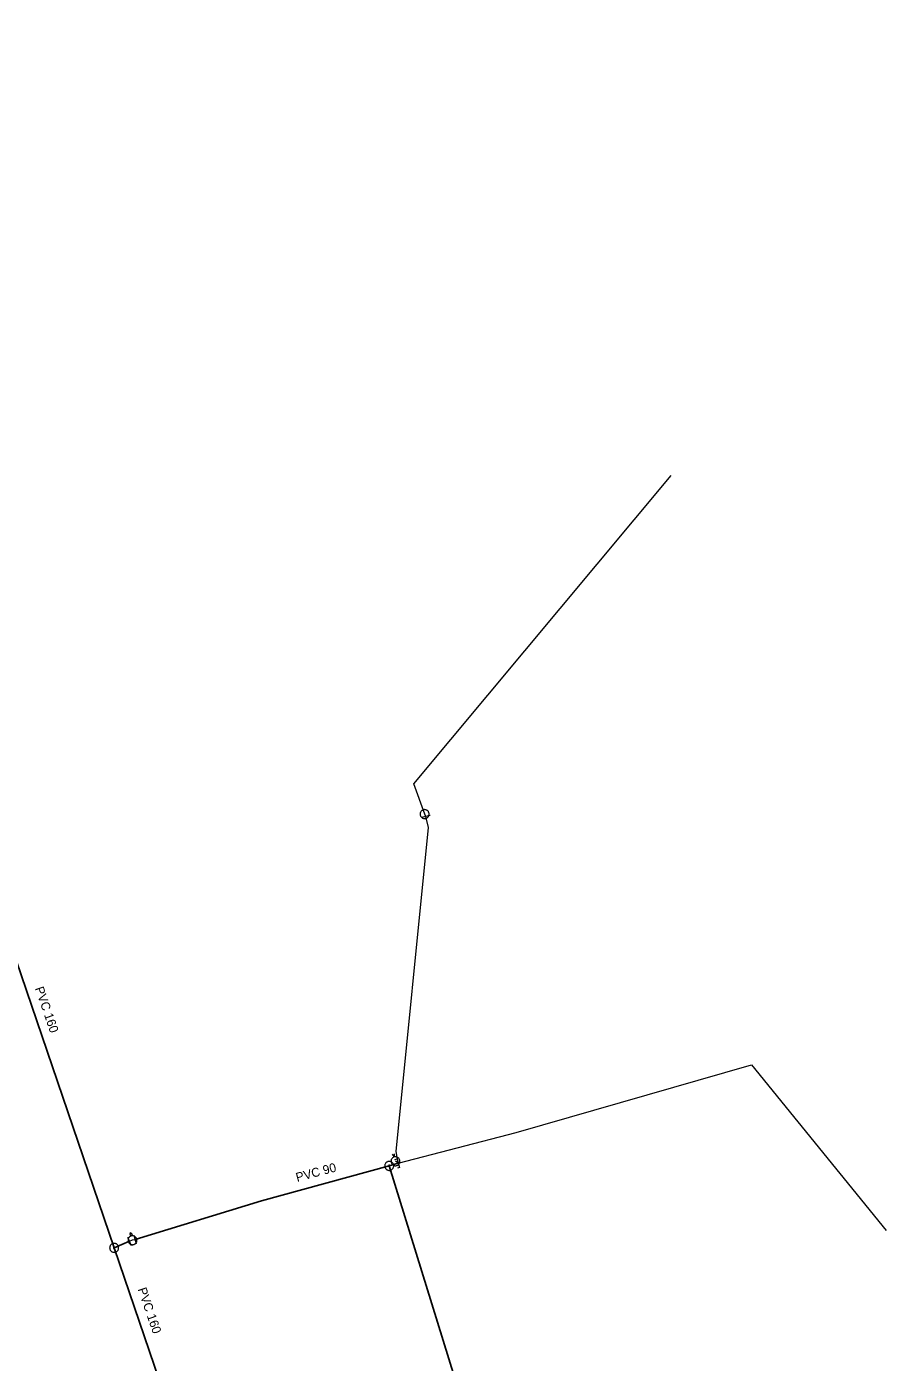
# Model space of a CAD drawing. Extents: x -659250 to -657316, y -997555 to -993684.
# Drawn here: x -658539.7 to -658443.8, y -995411.3 to -995262.3 of the extents above; entities that cross this region are included whole.
import ezdxf

# ---------------------------------------------------------------- set-up
doc = ezdxf.new("R2010")
doc.units = 0
doc.header["$LTSCALE"] = 0.4
doc.layers.add('1', color=7, linetype='Continuous')
for name, color, linetype, lineweight in [('13', 7, 'Continuous', 13), ('14', 7, 'Continuous', 25), ('17', 7, 'Continuous', 25), ('23', 7, 'Continuous', 13), ('34', 7, 'Continuous', 13), ('47', 7, 'Continuous', 13)]:
    doc.layers.add(name, color=color, linetype=linetype, lineweight=lineweight)

msp = doc.modelspace()

# ---------------------------------------------------------------- linework, layer by layer
at = {"layer": '13'}
for points in [[(-658495.287, -995350.184), (-658496.524, -995346.776), (-658467.787, -995312.381)], [(-658498.252, -995389.133), (-658498.48, -995387.811), (-658494.883, -995351.653), (-658495.19, -995350.441)], [(-658498.252, -995389.133), (-658485.079, -995385.693), (-658458.831, -995378.138), (-658443.765, -995396.647)]]:
    msp.add_lwpolyline(points, dxfattribs=at)
at = {"layer": '14', "lineweight": 13}
for p, q in [((-658495.19, -995350.441), (-658495.287, -995350.184)), ((-658498.252, -995389.133), (-658498.57, -995388.914))]:
    msp.add_line(p, q, dxfattribs=at)
msp.add_lwpolyline([(-658528.268, -995397.839), (-658527.915, -995397.698), (-658527.649, -995397.631)], dxfattribs=at)
at = {"layer": '17'}
for points in [[(-658529.982, -995398.576), (-658547.296, -995347.916), (-658562.807, -995322.499), (-658567.693, -995312.894), (-658572.046, -995279.881), (-658571.688, -995265.649), (-658570.911, -995262.293)], [(-658527.649, -995397.631), (-658513.52, -995393.331), (-658499.267, -995389.429), (-658498.252, -995389.133)], [(-658499.267, -995389.429), (-658490.855, -995416.603), (-658471.482, -995471.213), (-658463.591, -995473.78)], [(-658524.344, -995415.072), (-658529.982, -995398.576), (-658528.268, -995397.839)]]:
    msp.add_lwpolyline(points, dxfattribs=at)
at = {"layer": '23'}
msp.add_line((-658527.996, -995397.049), (-658528.185, -995397.099), dxfattribs=at)
for points in [[(-658494.93, -995349.852), (-658494.963, -995349.815), (-658495.002, -995349.779), (-658495.047, -995349.749), (-658495.092, -995349.723), (-658495.141, -995349.702), (-658495.19, -995349.685), (-658495.24, -995349.676), (-658495.293, -995349.671), (-658495.345, -995349.671), (-658495.397, -995349.677), (-658495.448, -995349.689), (-658495.498, -995349.704), (-658495.545, -995349.725), (-658495.591, -995349.752), (-658495.634, -995349.783), (-658495.672, -995349.818), (-658495.705, -995349.857), (-658495.736, -995349.9), (-658495.763, -995349.945), (-658495.784, -995349.994), (-658495.799, -995350.044), (-658495.81, -995350.094), (-658495.815, -995350.147), (-658495.816, -995350.198), (-658495.809, -995350.251), (-658495.797, -995350.301), (-658495.782, -995350.351), (-658495.76, -995350.398), (-658495.734, -995350.444), (-658495.703, -995350.487), (-658495.667, -995350.525), (-658495.628, -995350.56), (-658495.587, -995350.591), (-658495.54, -995350.616), (-658495.493, -995350.638), (-658495.443, -995350.653), (-658495.391, -995350.664), (-658495.339, -995350.669), (-658495.287, -995350.669)], [(-658495.799, -995350.044), (-658495.81, -995350.094), (-658495.815, -995350.147), (-658495.816, -995350.198), (-658495.809, -995350.251), (-658495.797, -995350.301), (-658495.782, -995350.351), (-658495.76, -995350.398), (-658495.734, -995350.444), (-658495.703, -995350.487), (-658495.667, -995350.525), (-658495.628, -995350.56), (-658495.587, -995350.591), (-658495.54, -995350.616), (-658495.493, -995350.638), (-658495.443, -995350.653), (-658495.391, -995350.664), (-658495.339, -995350.669), (-658495.287, -995350.669), (-658495.235, -995350.662), (-658495.184, -995350.652), (-658495.134, -995350.636), (-658495.086, -995350.614), (-658495.04, -995350.588), (-658495, -995350.556), (-658494.961, -995350.521), (-658494.926, -995350.483), (-658494.896, -995350.439), (-658494.87, -995350.394), (-658494.849, -995350.347), (-658494.833, -995350.297), (-658494.822, -995350.246), (-658494.816, -995350.193), (-658494.817, -995350.14), (-658494.823, -995350.089), (-658494.834, -995350.038), (-658494.85, -995349.989), (-658494.872, -995349.94), (-658494.898, -995349.896), (-658494.93, -995349.852)], [(-658495.134, -995350.636), (-658495.086, -995350.614), (-658495.04, -995350.588), (-658495, -995350.556), (-658494.961, -995350.521), (-658494.926, -995350.483), (-658494.896, -995350.439), (-658494.87, -995350.394), (-658494.849, -995350.347), (-658494.833, -995350.297), (-658494.822, -995350.246), (-658494.816, -995350.193), (-658494.817, -995350.14), (-658494.823, -995350.089), (-658494.834, -995350.038), (-658494.85, -995349.989), (-658494.872, -995349.94), (-658494.898, -995349.896), (-658494.93, -995349.852), (-658494.963, -995349.815), (-658495.002, -995349.779), (-658495.047, -995349.749), (-658495.092, -995349.723), (-658495.141, -995349.702), (-658495.19, -995349.685), (-658495.24, -995349.676), (-658495.293, -995349.671), (-658495.345, -995349.671), (-658495.397, -995349.677), (-658495.448, -995349.689), (-658495.498, -995349.704), (-658495.545, -995349.725), (-658495.591, -995349.752), (-658495.634, -995349.783), (-658495.672, -995349.818), (-658495.705, -995349.857), (-658495.736, -995349.9), (-658495.763, -995349.945), (-658495.784, -995349.994), (-658495.799, -995350.044)], [(-658495.287, -995350.669), (-658495.235, -995350.662), (-658495.184, -995350.652), (-658495.134, -995350.636)], [(-658498.703, -995388.07), (-658498.715, -995388.397), (-658498.901, -995388.127)], [(-658528.161, -995397.193), (-658528.198, -995397.049), (-658528.141, -995396.878), (-658528.009, -995396.999), (-658527.971, -995397.143)], [(-658527.449, -995397.593), (-658527.465, -995397.543), (-658527.487, -995397.495), (-658527.514, -995397.451), (-658527.545, -995397.409), (-658527.58, -995397.37), (-658527.62, -995397.335), (-658527.662, -995397.305), (-658527.707, -995397.28), (-658527.755, -995397.258), (-658527.804, -995397.242), (-658527.856, -995397.231), (-658527.909, -995397.226), (-658527.961, -995397.226), (-658528.012, -995397.232), (-658528.063, -995397.243), (-658528.114, -995397.26), (-658528.16, -995397.281), (-658528.207, -995397.308), (-658528.248, -995397.338), (-658528.287, -995397.373), (-658528.322, -995397.414), (-658528.352, -995397.456), (-658528.378, -995397.502), (-658528.4, -995397.549), (-658528.415, -995397.599), (-658528.425, -995397.651), (-658528.43, -995397.702), (-658528.43, -995397.755), (-658528.423, -995397.807), (-658528.413, -995397.858), (-658528.397, -995397.907), (-658528.375, -995397.955), (-658528.349, -995398.001), (-658528.318, -995398.043), (-658528.283, -995398.08), (-658528.243, -995398.115), (-658528.201, -995398.146), (-658528.155, -995398.173), (-658528.107, -995398.193)], [(-658528.207, -995397.308), (-658528.248, -995397.338), (-658528.287, -995397.373), (-658528.322, -995397.414), (-658528.352, -995397.456), (-658528.378, -995397.502), (-658528.4, -995397.549), (-658528.415, -995397.599), (-658528.425, -995397.651), (-658528.43, -995397.702), (-658528.43, -995397.755), (-658528.423, -995397.807), (-658528.413, -995397.858), (-658528.397, -995397.907), (-658528.375, -995397.955), (-658528.349, -995398.001), (-658528.318, -995398.043), (-658528.283, -995398.08), (-658528.243, -995398.115), (-658528.201, -995398.146), (-658528.155, -995398.173), (-658528.107, -995398.193), (-658528.058, -995398.209), (-658528.006, -995398.219), (-658527.955, -995398.226), (-658527.901, -995398.224), (-658527.85, -995398.218), (-658527.799, -995398.207), (-658527.75, -995398.19), (-658527.702, -995398.169), (-658527.656, -995398.143), (-658527.615, -995398.111), (-658527.575, -995398.076), (-658527.541, -995398.038), (-658527.511, -995397.994), (-658527.484, -995397.95), (-658527.464, -995397.902), (-658527.447, -995397.851), (-658527.437, -995397.8), (-658527.432, -995397.748)], [(-658528.107, -995398.193), (-658528.058, -995398.209), (-658528.006, -995398.219), (-658527.955, -995398.226), (-658527.901, -995398.224), (-658527.85, -995398.218), (-658527.799, -995398.207), (-658527.75, -995398.19), (-658527.702, -995398.169), (-658527.656, -995398.143), (-658527.615, -995398.111), (-658527.575, -995398.076), (-658527.541, -995398.038), (-658527.511, -995397.994), (-658527.484, -995397.95), (-658527.464, -995397.902), (-658527.447, -995397.851), (-658527.437, -995397.8), (-658527.432, -995397.748), (-658527.433, -995397.696), (-658527.438, -995397.644), (-658527.449, -995397.593), (-658527.465, -995397.543), (-658527.487, -995397.495), (-658527.514, -995397.451), (-658527.545, -995397.409), (-658527.58, -995397.37), (-658527.62, -995397.335), (-658527.662, -995397.305), (-658527.707, -995397.28), (-658527.755, -995397.258), (-658527.804, -995397.242), (-658527.856, -995397.231), (-658527.909, -995397.226), (-658527.961, -995397.226), (-658528.012, -995397.232), (-658528.063, -995397.243), (-658528.114, -995397.26), (-658528.16, -995397.281), (-658528.207, -995397.308)], [(-658527.432, -995397.748), (-658527.433, -995397.696), (-658527.438, -995397.644), (-658527.449, -995397.593)]]:
    msp.add_lwpolyline(points, dxfattribs=at)
msp.add_lwpolyline([(-658498.091, -995388.775), (-658498.118, -995388.703), (-658498.157, -995388.636), (-658498.204, -995388.575), (-658498.261, -995388.523), (-658498.326, -995388.48), (-658498.396, -995388.447), (-658498.47, -995388.426), (-658498.546, -995388.417), (-658498.623, -995388.419), (-658498.7, -995388.433), (-658498.772, -995388.459), (-658498.841, -995388.496), (-658498.902, -995388.543), (-658498.955, -995388.599), (-658498.998, -995388.663), (-658499.033, -995388.732), (-658499.056, -995388.806), (-658499.066, -995388.882), (-658499.065, -995388.959), (-658499.053, -995389.036), (-658499.027, -995389.108), (-658498.992, -995389.177), (-658498.945, -995389.24), (-658498.891, -995389.294), (-658498.828, -995389.339), (-658498.76, -995389.374), (-658498.686, -995389.398), (-658498.61, -995389.41), (-658498.532, -995389.41), (-658498.457, -995389.399), (-658498.382, -995389.375), (-658498.313, -995389.34), (-658498.25, -995389.296), (-658498.195, -995389.243), (-658498.149, -995389.18), (-658498.113, -995389.113), (-658498.087, -995389.04), (-658498.074, -995388.964), (-658498.072, -995388.886), (-658498.082, -995388.81)], close=True, dxfattribs=at)
at = {"layer": '34'}
for p, q in [((-658494.705, -995350.317), (-658495.674, -995350.563)), ((-658528.471, -995397.382), (-658528.065, -995398.295)), ((-658527.776, -995397.147), (-658527.522, -995398.114))]:
    msp.add_line(p, q, dxfattribs=at)
at = {"layer": '47'}
for points in [[(-658498.767, -995389.429), (-658498.77, -995389.377), (-658498.778, -995389.325), (-658498.792, -995389.275), (-658498.809, -995389.226), (-658498.834, -995389.179), (-658498.863, -995389.135), (-658498.896, -995389.095), (-658498.933, -995389.058), (-658498.973, -995389.025), (-658499.017, -995388.996), (-658499.064, -995388.972), (-658499.113, -995388.954), (-658499.163, -995388.94), (-658499.215, -995388.932), (-658499.267, -995388.929), (-658499.319, -995388.932), (-658499.371, -995388.94), (-658499.422, -995388.954), (-658499.47, -995388.972), (-658499.517, -995388.996), (-658499.561, -995389.025), (-658499.602, -995389.058), (-658499.639, -995389.095), (-658499.672, -995389.135), (-658499.7, -995389.179), (-658499.724, -995389.226), (-658499.743, -995389.275), (-658499.755, -995389.325), (-658499.764, -995389.377), (-658499.767, -995389.429), (-658499.764, -995389.481), (-658499.755, -995389.533), (-658499.743, -995389.584), (-658499.724, -995389.632), (-658499.7, -995389.679), (-658499.672, -995389.723), (-658499.639, -995389.764), (-658499.602, -995389.801), (-658499.561, -995389.834), (-658499.517, -995389.862), (-658499.47, -995389.886), (-658499.422, -995389.905), (-658499.371, -995389.918), (-658499.319, -995389.926), (-658499.267, -995389.929), (-658499.215, -995389.926), (-658499.163, -995389.918), (-658499.113, -995389.905), (-658499.064, -995389.886), (-658499.017, -995389.862), (-658498.973, -995389.834), (-658498.933, -995389.801), (-658498.896, -995389.764), (-658498.863, -995389.723), (-658498.834, -995389.679), (-658498.809, -995389.632), (-658498.792, -995389.584), (-658498.778, -995389.533), (-658498.77, -995389.481)], [(-658499.184, -995389.429), (-658499.184, -995389.42), (-658499.187, -995389.412), (-658499.189, -995389.404), (-658499.192, -995389.396), (-658499.196, -995389.388), (-658499.201, -995389.381), (-658499.206, -995389.374), (-658499.212, -995389.368), (-658499.219, -995389.363), (-658499.226, -995389.358), (-658499.233, -995389.354), (-658499.242, -995389.351), (-658499.25, -995389.349), (-658499.258, -995389.347), (-658499.267, -995389.347), (-658499.276, -995389.347), (-658499.284, -995389.349), (-658499.292, -995389.351), (-658499.3, -995389.354), (-658499.308, -995389.358), (-658499.315, -995389.363), (-658499.322, -995389.368), (-658499.328, -995389.374), (-658499.334, -995389.381), (-658499.338, -995389.388), (-658499.342, -995389.396), (-658499.345, -995389.404), (-658499.347, -995389.412), (-658499.349, -995389.42), (-658499.349, -995389.429), (-658499.349, -995389.438), (-658499.347, -995389.446), (-658499.345, -995389.454), (-658499.342, -995389.462), (-658499.338, -995389.47), (-658499.334, -995389.477), (-658499.328, -995389.484), (-658499.322, -995389.49), (-658499.315, -995389.496), (-658499.308, -995389.5), (-658499.3, -995389.504), (-658499.292, -995389.507), (-658499.284, -995389.509), (-658499.276, -995389.511), (-658499.267, -995389.511), (-658499.258, -995389.511), (-658499.25, -995389.509), (-658499.242, -995389.507), (-658499.233, -995389.504), (-658499.226, -995389.5), (-658499.219, -995389.496), (-658499.212, -995389.49), (-658499.206, -995389.484), (-658499.201, -995389.477), (-658499.196, -995389.47), (-658499.192, -995389.462), (-658499.189, -995389.454), (-658499.187, -995389.446), (-658499.184, -995389.438)], [(-658529.483, -995398.576), (-658529.486, -995398.524), (-658529.494, -995398.472), (-658529.508, -995398.422), (-658529.526, -995398.373), (-658529.55, -995398.326), (-658529.579, -995398.282), (-658529.612, -995398.242), (-658529.649, -995398.205), (-658529.689, -995398.172), (-658529.733, -995398.143), (-658529.78, -995398.119), (-658529.829, -995398.101), (-658529.879, -995398.087), (-658529.931, -995398.079), (-658529.983, -995398.076), (-658530.035, -995398.079), (-658530.087, -995398.087), (-658530.138, -995398.101), (-658530.186, -995398.119), (-658530.233, -995398.143), (-658530.277, -995398.172), (-658530.318, -995398.205), (-658530.355, -995398.242), (-658530.388, -995398.282), (-658530.416, -995398.326), (-658530.44, -995398.373), (-658530.459, -995398.422), (-658530.472, -995398.472), (-658530.48, -995398.524), (-658530.483, -995398.576), (-658530.48, -995398.628), (-658530.472, -995398.68), (-658530.459, -995398.731), (-658530.44, -995398.779), (-658530.416, -995398.826), (-658530.388, -995398.87), (-658530.355, -995398.911), (-658530.318, -995398.948), (-658530.277, -995398.981), (-658530.233, -995399.009), (-658530.186, -995399.033), (-658530.138, -995399.052), (-658530.087, -995399.065), (-658530.035, -995399.073), (-658529.983, -995399.076), (-658529.931, -995399.073), (-658529.879, -995399.065), (-658529.829, -995399.052), (-658529.78, -995399.033), (-658529.733, -995399.009), (-658529.689, -995398.981), (-658529.649, -995398.948), (-658529.612, -995398.911), (-658529.579, -995398.87), (-658529.55, -995398.826), (-658529.526, -995398.779), (-658529.508, -995398.731), (-658529.494, -995398.68), (-658529.486, -995398.628)], [(-658529.901, -995398.576), (-658529.901, -995398.567), (-658529.903, -995398.559), (-658529.905, -995398.551), (-658529.908, -995398.543), (-658529.912, -995398.535), (-658529.917, -995398.528), (-658529.922, -995398.521), (-658529.928, -995398.515), (-658529.935, -995398.51), (-658529.942, -995398.505), (-658529.95, -995398.501), (-658529.958, -995398.498), (-658529.966, -995398.496), (-658529.974, -995398.494), (-658529.983, -995398.494), (-658529.992, -995398.494), (-658530, -995398.496), (-658530.008, -995398.498), (-658530.016, -995398.501), (-658530.024, -995398.505), (-658530.031, -995398.51), (-658530.038, -995398.515), (-658530.044, -995398.521), (-658530.05, -995398.528), (-658530.054, -995398.535), (-658530.058, -995398.543), (-658530.061, -995398.551), (-658530.063, -995398.559), (-658530.065, -995398.567), (-658530.065, -995398.576), (-658530.065, -995398.585), (-658530.063, -995398.593), (-658530.061, -995398.601), (-658530.058, -995398.609), (-658530.054, -995398.617), (-658530.05, -995398.624), (-658530.044, -995398.631), (-658530.038, -995398.637), (-658530.031, -995398.643), (-658530.024, -995398.647), (-658530.016, -995398.651), (-658530.008, -995398.654), (-658530, -995398.656), (-658529.992, -995398.658), (-658529.983, -995398.658), (-658529.974, -995398.658), (-658529.966, -995398.656), (-658529.958, -995398.654), (-658529.95, -995398.651), (-658529.942, -995398.647), (-658529.935, -995398.643), (-658529.928, -995398.637), (-658529.922, -995398.631), (-658529.917, -995398.624), (-658529.912, -995398.617), (-658529.908, -995398.609), (-658529.905, -995398.601), (-658529.903, -995398.593), (-658529.901, -995398.585)]]:
    msp.add_lwpolyline(points, close=True, dxfattribs=at)
msp.add_lwpolyline([(-658498.632, -995388.727), (-658498.39, -995388.656), (-658498.113, -995389.609), (-658498.354, -995389.679)], dxfattribs=at)

# ---------------------------------------------------------------- texts
at = {"layer": '1'}
for s, rotation, p in [('PVC 160 ', 289, (-658538.839, -995369.614)), ('PVC 90', 15, (-658509.546, -995391.221)), ('PVC 160 ', 289, (-658527.363, -995403.192))]:
    msp.add_text(s, height=1, rotation=rotation, dxfattribs=at).set_placement(p)

doc.saveas('drawing.dxf')
